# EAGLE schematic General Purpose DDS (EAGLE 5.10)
MFG: Kemet; PN: A700V106M016ATE045

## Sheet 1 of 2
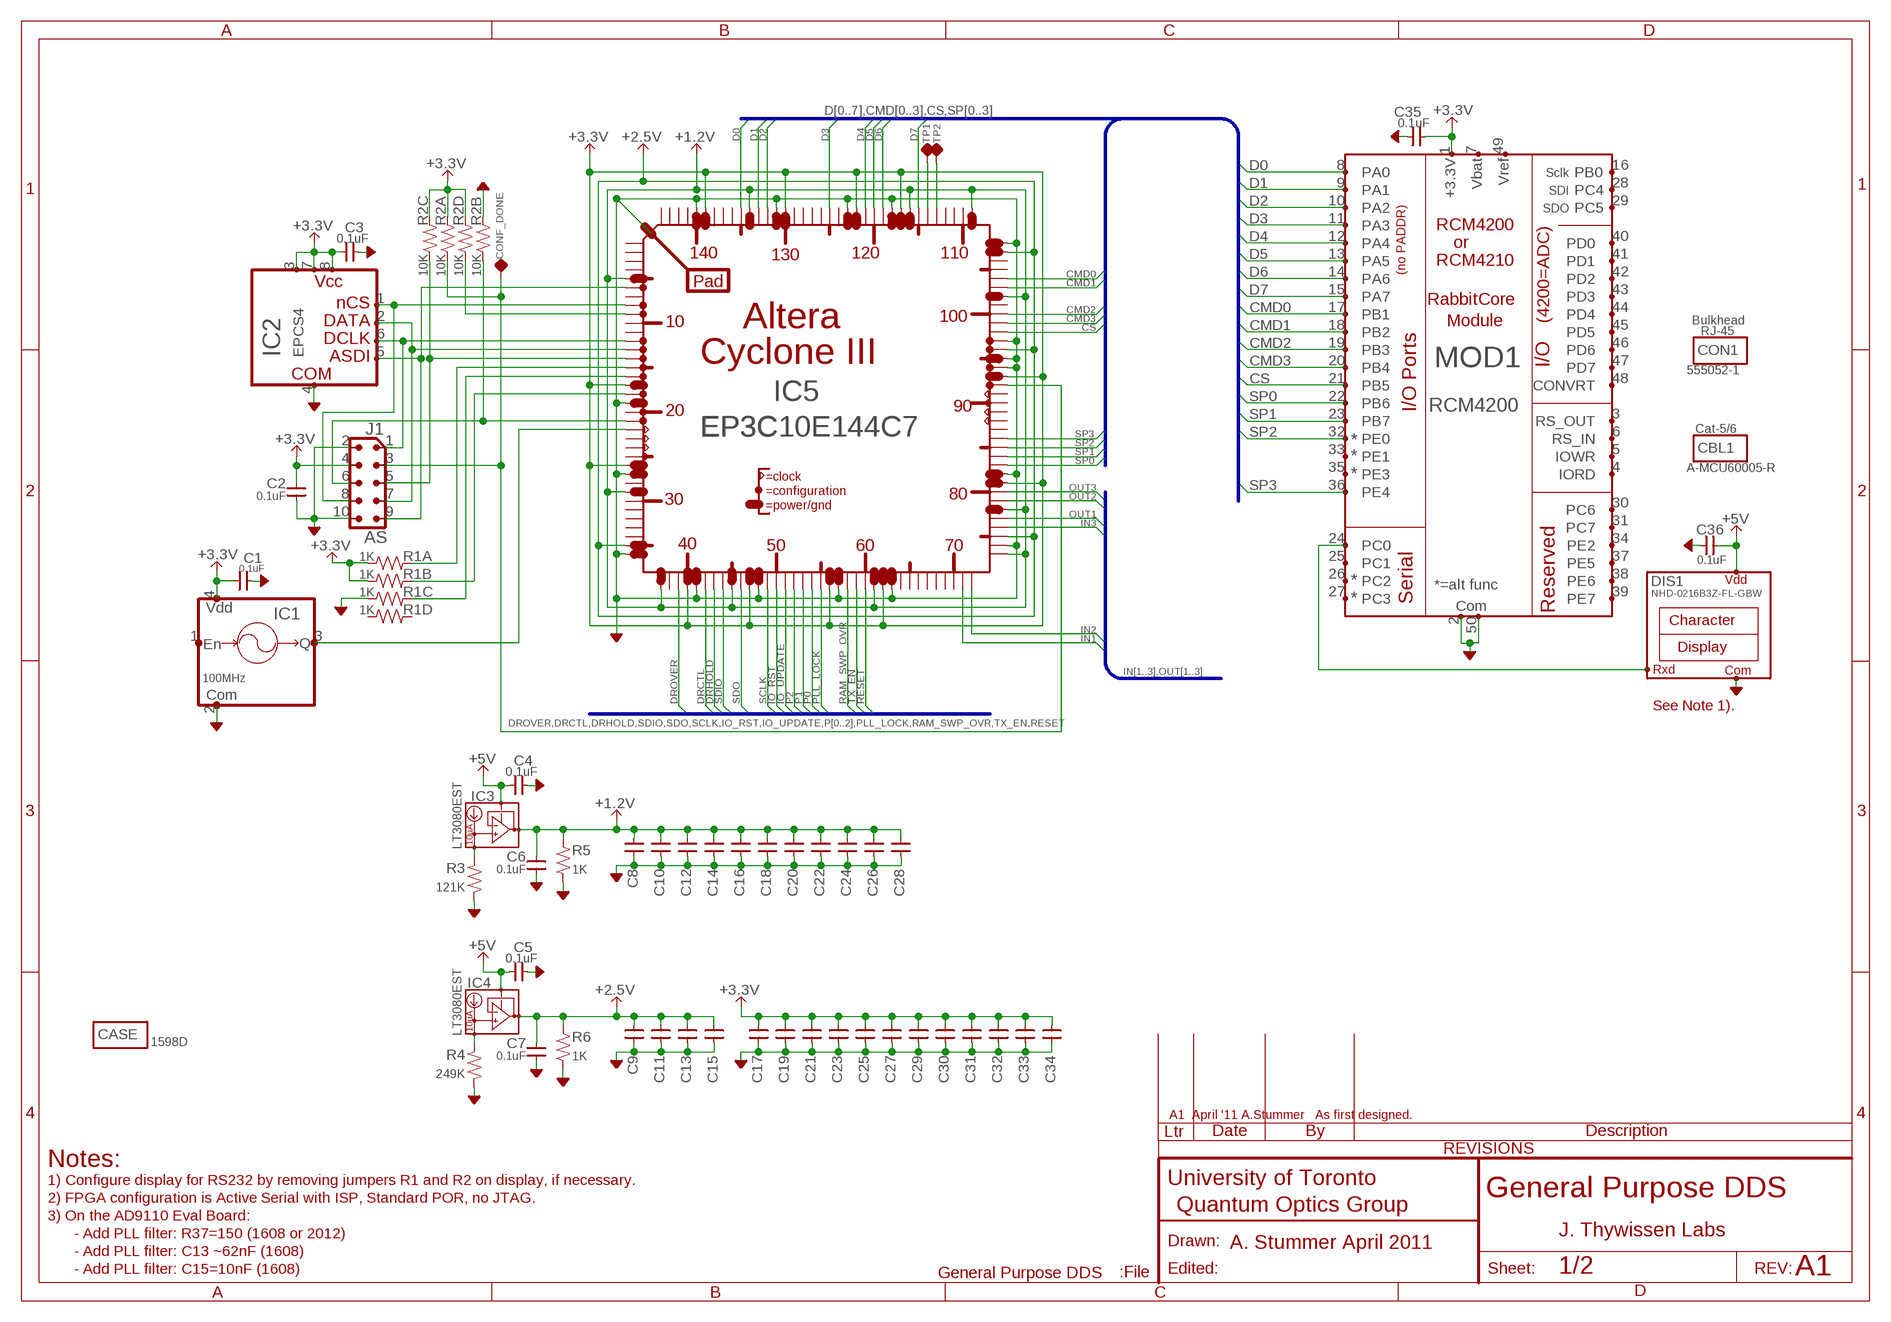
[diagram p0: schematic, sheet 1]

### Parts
C1  0.1uF  CAP-H-0805  [2012(0805)]
C2  0.1uF  CAP-V-0805  [2012(0805)]
C3  0.1uF  CAP-H-0805  [2012(0805)]
C4  0.1uF  CAP-H-0805  [2012(0805)]
C5  0.1uF  CAP-H-0805  [2012(0805)]
C6  0.1uF  CAP-V-0805  [2012(0805)]
C7  0.1uF  CAP-V-0805  [2012(0805)]
C8  0.1uF  CAP-V-0603  [1608(0603)]
C9  0.1uF  CAP-V-0603  [1608(0603)]
C10  0.1uF  CAP-V-0603  [1608(0603)]
C11  0.1uF  CAP-V-0603  [1608(0603)]
C12  0.1uF  CAP-V-0603  [1608(0603)]
C13  0.1uF  CAP-V-0603  [1608(0603)]
C14  0.1uF  CAP-V-0603  [1608(0603)]
C15  0.1uF  CAP-V-0603  [1608(0603)]
C16  0.1uF  CAP-V-0603  [1608(0603)]
C17  0.1uF  CAP-V-0603  [1608(0603)]
C18  0.1uF  CAP-V-0603  [1608(0603)]
C19  0.1uF  CAP-V-0603  [1608(0603)]
C20  0.1uF  CAP-V-0603  [1608(0603)]
C21  0.1uF  CAP-V-0603  [1608(0603)]
C22  0.1uF  CAP-V-0603  [1608(0603)]
C23  0.1uF  CAP-V-0603  [1608(0603)]
C24  0.1uF  CAP-V-0603  [1608(0603)]
C25  0.1uF  CAP-V-0603  [1608(0603)]
C26  0.1uF  CAP-V-0603  [1608(0603)]
C27  0.1uF  CAP-V-0603  [1608(0603)]
C28  0.1uF  CAP-V-0603  [1608(0603)]
C29  0.1uF  CAP-V-0603  [1608(0603)]
C30  0.1uF  CAP-V-0603  [1608(0603)]
C31  0.1uF  CAP-V-0603  [1608(0603)]
C32  0.1uF  CAP-V-0603  [1608(0603)]
C33  0.1uF  CAP-V-0603  [1608(0603)]
C34  0.1uF  CAP-V-0603  [1608(0603)]
C35  0.1uF  CAP-H-0805  [2012(0805)]
C36  0.1uF  CAP-H-0805  [2012(0805)]
CASE  1598D  MISC  [MISC]
CBL1  A-MCU60005-R  MISC  [MISC]
CON1  555052-1  MISC  [MISC]
CONF_DONE  TP-0.042B  [TP-0.042B]
DIS1  NHD-0216B3Z-FL-GBW  DISPLAY:3WIRE  [DISPLAY:3WIRE]
IC1  100MHz  OSCILLATOR:CX750(CITIZEN)-CITIZEN_CSX  [CSX750(CITIZEN_OSC)]
IC2  EPCS4  MEMORY-EPCS1-4(ALTERACONFIG)  [SOIC-8@1]
IC3  LT3080EST  REGULATOR:LT3080(3PIN,LDO,I-SET)-SOT223  [SOT223(C)]
IC4  LT3080EST  REGULATOR:LT3080(3PIN,LDO,I-SET)-SOT223  [SOT223(C)]
IC5  EP3C10E144C7  FPGA_EP3C_T144(CYCLONE3)  [EQFP144(TQFP_WITH_GROUND_PAD)]
J1  CONN-2X5-BLASTER  [CONN-2X5-BLASTER]
MOD1  RCM4200  RABBIT_RCM4200-THROUGH1  [RABBIT_RCM42XX(THRU)]
R1  1K  R-4PAK-0603  [PANASONIC_EXB-V8V(QUAD-R-PACK)]
R2  10K  R-4PAK-0603  [PANASONIC_EXB-V8V(QUAD-R-PACK)]
R3  121K  R-V-0805  [2012(0805)]
R4  249K  R-V-0805  [2012(0805)]
R5  1K  R-V-0805  [2012(0805)]
R6  1K  R-V-0805  [2012(0805)]
TP1  TP-0.042B  [TP-0.042B]
TP2  TP-0.042B  [TP-0.042B]

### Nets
+1.2V: C6.2 C8.2 C10.2 C12.2 C14.2 C16.2 C18.2 C20.2 C22.2 C24.2 C26.2 C28.2 IC3.2(OUT) IC5.5 IC5.29 IC5.37 IC5.45 IC5.61 IC5.73 IC5.78 IC5.102 IC5.109 IC5.116 IC5.134 R5.2
+2.5V: C7.2 C9.2 C11.2 C13.2 C15.2 IC4.2(OUT) IC5.35 IC5.75 IC5.96 IC5.107 R6.2
+3.3V: C1.1 C2.2 C3.1 C17.2 C19.2 C21.2 C23.2 C25.2 C27.2 C29.2 C30.2 C31.2 C32.2 C33.2 C34.2 C35.1 IC1.4(VDD) IC2.3(VCC1) IC2.7(VCC2) IC2.8(VCC3) IC5.17 IC5.26 IC5.40 IC5.47 IC5.56 IC5.62 IC5.81 IC5.93 IC5.117 IC5.122 IC5.130 IC5.139 J1.4 MOD1.1(+3.3V) R1.1A R1.2A R2.1B R2.3B R2.4B ; also sheet 2
+5V: C4.1 C5.1 C36.1 DIS1.VDD IC3.3(IN) IC4.3(IN) ; also sheet 2
AGND: C1.2 C2.1 C3.2 C4.2 C5.2 C6.1 C7.1 C8.1 C9.1 C10.1 C11.1 C12.1 C13.1 C14.1 C15.1 C16.1 C17.1 C18.1 C19.1 C20.1 C21.1 C22.1 C23.1 C24.1 C25.1 C26.1 C27.1 C28.1 C29.1 C30.1 C31.1 C32.1 C33.1 C34.1 C35.2 C36.2 DIS1.COM IC1.2(COM) IC2.4(COM) IC5.19 IC5.27 IC5.36 IC5.41 IC5.48 IC5.57 IC5.63 IC5.74 IC5.82 IC5.94 IC5.95 IC5.97 IC5.108 IC5.118 IC5.123 IC5.131 IC5.140 IC5.PAD J1.2 J1.10 MOD1.2(COM1) MOD1.50(COM2) R1.3A R2.2B R3.1 R4.1 R5.1 R6.1 ; also sheet 2
CMD0: IC5.104 MOD1.17(PB1)
CMD1: IC5.103 MOD1.18(PB2)
CMD2: IC5.100 MOD1.19(PB3)
CMD3: IC5.99 MOD1.20(PB4)
CONF_DONE: CONF_DONE.TP IC5.92 J1.3 R2.1A
CS: IC5.98 MOD1.21(PB5)
D0: IC5.135 MOD1.8(PA0)
D1: IC5.133 MOD1.9(PA1)
D2: IC5.132 MOD1.10(PA2)
D3: IC5.125 MOD1.11(PA3)
D4: IC5.121 MOD1.12(PA4)
D5: IC5.120 MOD1.13(PA5)
D6: IC5.119 MOD1.14(PA6)
D7: IC5.115 MOD1.15(PA7)
DRCTL: IC5.42 ; also sheet 2
DRHOLD: IC5.43 ; also sheet 2
DROVER: IC5.39 ; also sheet 2
IN1: IC5.71 ; also sheet 2
IN2: IC5.72 ; also sheet 2
IN3: IC5.76 ; also sheet 2
IO_RST: IC5.50 ; also sheet 2
IO_UPDATE: IC5.51 ; also sheet 2
N$1: IC2.2(DATA) IC5.13 J1.7
N$2: IC2.6(DCLK) IC5.12 J1.1
N$3: IC2.1(NCS) IC5.8 J1.8
N$4: IC2.5(ASDI) IC5.6 J1.9
N$6: IC5.14 J1.5 R2.3A
N$7: IC5.21 J1.6 R2.2A
N$9: IC5.16 R1.3B
N$11: IC5.9 R2.4A
N$12: IC5.18 R1.2B
N$13: IC5.15 R1.1B
N$16: IC1.3(Q) IC5.22
N$29: IC3.1(SET) R3.2
N$30: DIS1.RXD MOD1.24(PC0)
N$32: IC4.1(SET) R4.2
N$62: IC5.114 TP1.TP
N$66: IC5.113 TP2.TP
OUT1: IC5.77 ; also sheet 2
OUT2: IC5.79 ; also sheet 2
OUT3: IC5.80 ; also sheet 2
P0: IC5.54 ; also sheet 2
P1: IC5.53 ; also sheet 2
P2: IC5.52 ; also sheet 2
PLL_LOCK: IC5.55 ; also sheet 2
RAM_SWP_OVR: IC5.58 ; also sheet 2
RESET: IC5.60 ; also sheet 2
SCLK: IC5.49 ; also sheet 2
SDIO: IC5.44 ; also sheet 2
SDO: IC5.46 ; also sheet 2
SP0: IC5.83 MOD1.22(PB6)
SP1: IC5.84 MOD1.23(PB7)
SP2: IC5.85 MOD1.32(PE0)
SP3: IC5.86 MOD1.36(PE4)
TX_EN: IC5.59 ; also sheet 2
Unconnected: IC1.1(EN) IC5.1 IC5.2 IC5.3 IC5.4 IC5.7 IC5.10 IC5.11 IC5.20 IC5.23 IC5.24 IC5.25 IC5.28 IC5.30 IC5.31 IC5.32 IC5.33 IC5.34 IC5.38 IC5.64 IC5.65 IC5.66 IC5.67 IC5.68 IC5.69 IC5.70 IC5.87 IC5.88 IC5.89 IC5.90 IC5.91 IC5.101 IC5.105 IC5.106 IC5.110 IC5.111 IC5.112 IC5.124 IC5.126 IC5.127 IC5.128 IC5.129 IC5.136 IC5.137 IC5.138 IC5.141 IC5.142 IC5.143 IC5.144 MOD1.3(RS_OUT) MOD1.4(IORD) MOD1.5(IOWR) MOD1.6(RS_IN) MOD1.7(VBAT) MOD1.16(PB0) MOD1.25(PC1) MOD1.26(PC2) MOD1.27(PC3) MOD1.28(PC4) MOD1.29(PC5) MOD1.30(PC6) MOD1.31(PC7) MOD1.33(PE1) MOD1.34(PE2) MOD1.35(PE3) MOD1.37(PE5) MOD1.38(PE6) MOD1.39(PE7) MOD1.40(PD0) MOD1.41(PD1) MOD1.42(PD2) MOD1.43(PD3) MOD1.44(PD4) MOD1.45(PD5) MOD1.46(PD6) MOD1.47(PD7) MOD1.48(CONVRT) MOD1.49(VREF) R1.4A R1.4B

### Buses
DROVER,DRCTL,DRHOLD,SDIO,SDO,SCLK,IO_RST,IO_UPDATE,P[0..2],PLL_LOCK,RAM_SWP_OVR,TX_EN,RESET
RABBIT:D[0..7],CMD[0..3],CS,SP[0..3]
IN[1..3],OUT[1..3]
D[0..7],CMD[0..3],CS,SP[0..3]

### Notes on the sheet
- Bulkhead
- RJ-45
- Cat-5/6
- AS
- See Note 1).
- A1  April '11 A.Stummer   As first designed.
- Notes:
- 1) Configure display for RS232 by removing jumpers R1 and R2 on display, if necessary.
- General Purpose DDS
- 2) FPGA configuration is Active Serial with ISP, Standard POR, no JTAG.
- 3) On the AD9110 Eval Board:
- - Add PLL filter: R37=150 (1608 or 2012) | J. Thywissen Labs
- A. Stummer April 2011
- - Add PLL filter: C13 ~62nF (1608)
- - Add PLL filter: C15=10nF (1608) | A1

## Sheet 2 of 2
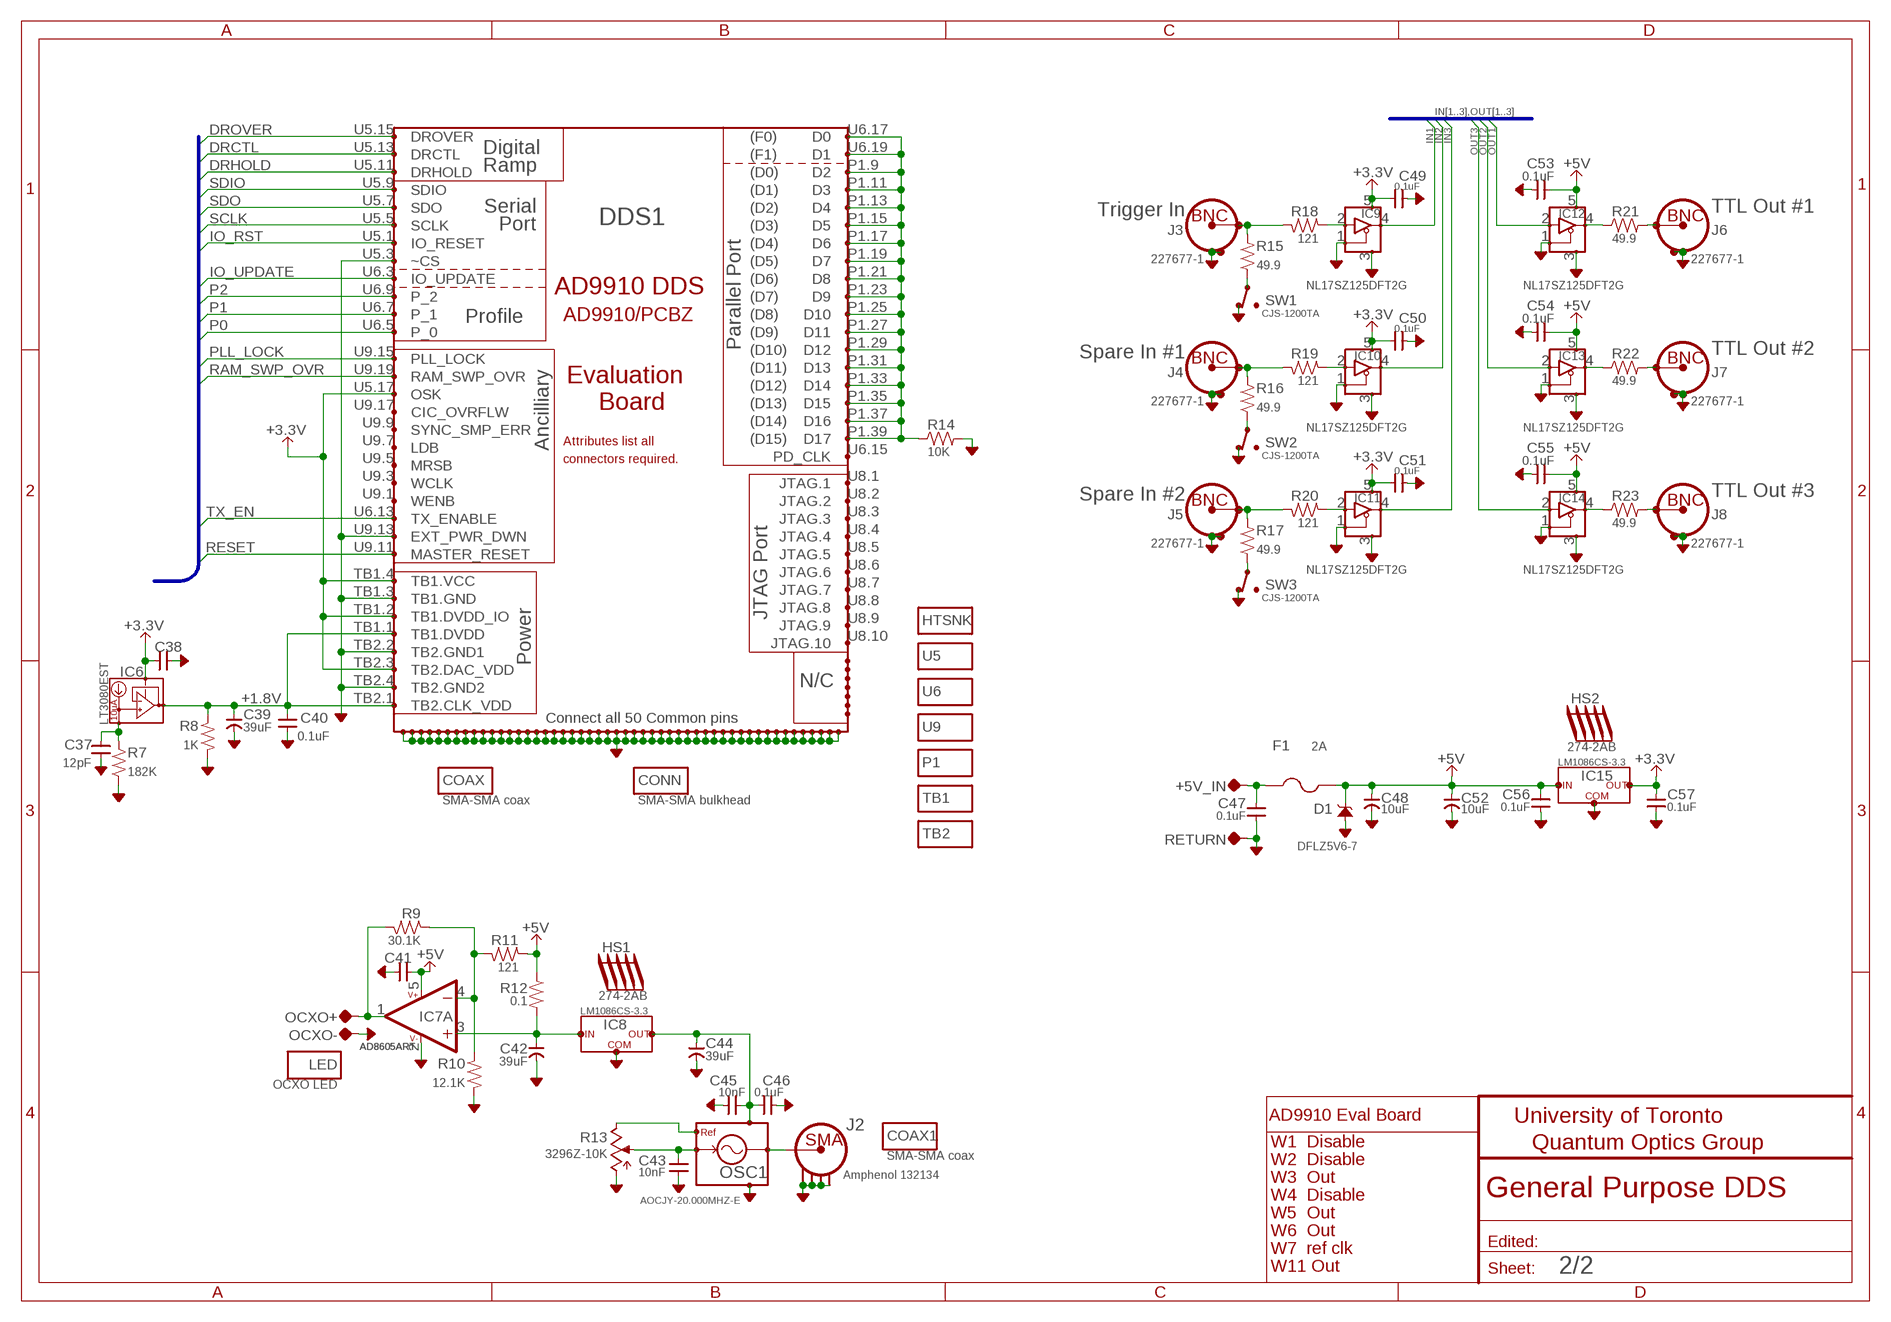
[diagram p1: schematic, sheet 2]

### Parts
+5V_IN  TP-0.042B  [TP-0.042B]
C37  12pF  CAP-H-0805  [2012(0805)]
C38  0.1uF  CAP-H-0805  [2012(0805)]
C39  39uF  CAP-POL--NIPPONCHEM_E61  [CAP:NIPPONCHEM_E61]
C40  0.1uF  CAP-H-0805  [2012(0805)]
C41  0.1uF  CAP-H-0805  [2012(0805)]
C42  39uF  CAP-POL--NIPPONCHEM_E61  [CAP:NIPPONCHEM_E61]
C43  10nF  CAP-H-0805  [2012(0805)]
C44  39uF  CAP-POL--NIPPONCHEM_E61  [CAP:NIPPONCHEM_E61]
C45  10nF  CAP-H-0805  [2012(0805)]
C46  0.1uF  CAP-H-0805  [2012(0805)]
C47  0.1uF  CAP-V-0805  [2012(0805)]
C48  10uF  CAP-POL-EIA-7343-13  [EIA-7343]
C49  0.1uF  CAP-H-0805  [2012(0805)]
C50  0.1uF  CAP-H-0805  [2012(0805)]
C51  0.1uF  CAP-H-0805  [2012(0805)]
C52  10uF  CAP-POL-EIA-7343-13  [EIA-7343]
C53  0.1uF  CAP-H-0805  [2012(0805)]
C54  0.1uF  CAP-H-0805  [2012(0805)]
C55  0.1uF  CAP-H-0805  [2012(0805)]
C56  0.1uF  CAP-V-0805  [2012(0805)]
C57  0.1uF  CAP-V-0805  [2012(0805)]
COAX  SMA-SMA coax  MISC  [MISC]
COAX1  SMA-SMA coax  MISC  [MISC]
CONN  SMA-SMA bulkhead  MISC  [MISC]
D1  DFLZ5V6-7  ZENER-DFLZ  [ZENER:DFLZ_V_(1W)]
DDS1  DDS:AD9910,EVALBOARD  [DDS:AD9910,EVALBOARD]
F1  2A  FUSE-5X20-4  [FUSE]
HS1  274-2AB  HEATSINK-1-274AB  [HEATSINK:274-2AB(WAKEFIELD,25C/W)]
HS2  274-2AB  HEATSINK-1-274AB  [HEATSINK:274-2AB(WAKEFIELD,25C/W)]
HTSNK  MISC  [MISC]
IC6  LT3080EST  REGULATOR:LT3080(3PIN,LDO,I-SET)-SOT223  [SOT223(C)]
IC7  AD8605ART  OPAMP-SOT23-5  [SOT23-5]
IC8  LM1086CS-3.3  REGULATOR:LM1086(LDO)-TO263  [TO263]
IC9  NL17SZ125DFT2G  LOGIC,BUFFER:NL17SZ125/16(SINGLE,BI-TRI-STATE)-SOT353  [SOT353]
IC10  NL17SZ125DFT2G  LOGIC,BUFFER:NL17SZ125/16(SINGLE,BI-TRI-STATE)-SOT353  [SOT353]
IC11  NL17SZ125DFT2G  LOGIC,BUFFER:NL17SZ125/16(SINGLE,BI-TRI-STATE)-SOT353  [SOT353]
IC12  NL17SZ125DFT2G  LOGIC,BUFFER:NL17SZ125/16(SINGLE,BI-TRI-STATE)-SOT353  [SOT353]
IC13  NL17SZ125DFT2G  LOGIC,BUFFER:NL17SZ125/16(SINGLE,BI-TRI-STATE)-SOT353  [SOT353]
IC14  NL17SZ125DFT2G  LOGIC,BUFFER:NL17SZ125/16(SINGLE,BI-TRI-STATE)-SOT353  [SOT353]
IC15  LM1086CS-3.3  REGULATOR:LM1086(LDO)-TO263  [TO263]
J2  Amphenol 132134  CONN:SMA  [CONN:SMA1]
J3  227677-1  CONN-BNCTYPE3HORIZ  [CONN-BNC-AMP-TYPE3HORIZ]
J4  227677-1  CONN-BNCTYPE3HORIZ  [CONN-BNC-AMP-TYPE3HORIZ]
J5  227677-1  CONN-BNCTYPE3HORIZ  [CONN-BNC-AMP-TYPE3HORIZ]
J6  227677-1  CONN-BNCTYPE3HORIZ  [CONN-BNC-AMP-TYPE3HORIZ]
J7  227677-1  CONN-BNCTYPE3HORIZ  [CONN-BNC-AMP-TYPE3HORIZ]
J8  227677-1  CONN-BNCTYPE3HORIZ  [CONN-BNC-AMP-TYPE3HORIZ]
LED  OCXO LED  MISC  [MISC]
OCXO+  TP-0.042B  [TP-0.042B]
OCXO-  TP-0.042B  [TP-0.042B]
OSC1  AOCJY-20.000MHZ-E  OSCILLATOR:AOCJY(ABRACON-OCXO)  [OSCILLATOR:AOCJY(ABRACON-OCXO)]
P1  MISC  [MISC]
R7  182K  R-V-0805  [2012(0805)]
R8  1K  R-V-0805  [2012(0805)]
R9  30.1K  R-H-0805  [2012(0805)]
R10  12.1K  R-V-0805  [2012(0805)]
R11  121  R-H-0805  [2012(0805)]
R12  0.1  R-H-0805  [2012(0805)]
R13  3296Z-10K  POT-BOURNS_3296Y  [BOURNS:3296Y]
R14  10K  R-H-0805  [2012(0805)]
R15  49.9  R-V-0805  [2012(0805)]
R16  49.9  R-V-0805  [2012(0805)]
R17  49.9  R-V-0805  [2012(0805)]
R18  121  R-H-0805  [2012(0805)]
R19  121  R-H-0805  [2012(0805)]
R20  121  R-H-0805  [2012(0805)]
R21  49.9  R-H-0805  [2012(0805)]
R22  49.9  R-H-0805  [2012(0805)]
R23  49.9  R-H-0805  [2012(0805)]
RETURN  TP-0.042B  [TP-0.042B]
SW1  CJS-1200TA  SWITCH:SPDT_CJS-1200A1  [SWITCH:SPDT-DIP(COPAL)]
SW2  CJS-1200TA  SWITCH:SPDT_CJS-1200A1  [SWITCH:SPDT-DIP(COPAL)]
SW3  CJS-1200TA  SWITCH:SPDT_CJS-1200A1  [SWITCH:SPDT-DIP(COPAL)]
TB1  MISC  [MISC]
TB2  MISC  [MISC]
U5  MISC  [MISC]
U6  MISC  [MISC]
U9  MISC  [MISC]

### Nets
+1.8V [Power]: C39.POS C40.1 DDS1.TB1.1(TB1.DVDD) DDS1.TB2.1(TB2.CLK_VDD) IC6.2(OUT) R8.2
+3.3V: C38.1 C49.1 C50.1 C51.1 C57.2 DDS1.TB1.2(TB1.DVDD_IO) DDS1.TB1.4(TB1.VCC) DDS1.TB2.3(TB2.DAC_VDD) DDS1.U5.17(OSK) IC6.3(IN) IC9.5(VDD) IC10.5(VDD) IC11.5(VDD) IC15.2(OUT) ; also sheet 1
+5V: C41.1 C48.+(POS) C52.+(POS) C53.1 C54.1 C55.1 C56.2 D1.C F1.2A IC7.5(B:V++) IC12.5(VDD) IC13.5(VDD) IC14.5(VDD) IC15.3(VI) R11.1 R12.1 ; also sheet 1
AGND: C37.2 C38.2 C39.NEG C40.2 C41.2 C42.NEG C43.2 C44.NEG C45.2 C46.2 C47.1 C48.-(NEG) C49.2 C50.2 C51.2 C52.-(NEG) C53.2 C54.2 C55.2 C56.1 C57.1 D1.A DDS1.P1.2(G1) DDS1.P1.4(G2) DDS1.P1.6(G3) DDS1.P1.8(G4) DDS1.P1.10(G5) DDS1.P1.12(G6) DDS1.P1.14(G7) DDS1.P1.16(G8) DDS1.P1.18(G9) DDS1.P1.20(G10) DDS1.P1.22(G11) DDS1.P1.24(G12) DDS1.P1.26(G13) DDS1.P1.28(G14) DDS1.P1.30(G15) DDS1.P1.32(G16) DDS1.P1.34(G17) DDS1.P1.36(G18) DDS1.P1.38(G19) DDS1.P1.40(G20) DDS1.TB1.3(TB1.GND) DDS1.TB2.2(TB2.GND1) DDS1.TB2.4(TB2.GND2) DDS1.U5.2(G31) DDS1.U5.3(~CS) DDS1.U5.4(G32) DDS1.U5.6(G33) DDS1.U5.8(G34) DDS1.U5.10(G35) DDS1.U5.12(G36) DDS1.U5.14(G37) DDS1.U5.16(G38) DDS1.U5.18(G39) DDS1.U5.20(G40) DDS1.U6.2(G21) DDS1.U6.4(G22) DDS1.U6.6(G23) DDS1.U6.8(G24) DDS1.U6.10(G25) DDS1.U6.12(G26) DDS1.U6.14(G27) DDS1.U6.16(G28) DDS1.U6.18(G29) DDS1.U6.20(G30) DDS1.U9.2(G41) DDS1.U9.4(G42) DDS1.U9.6(G43) DDS1.U9.8(G44) DDS1.U9.10(G45) DDS1.U9.12(G46) DDS1.U9.13(EXT_PWR_DWN) DDS1.U9.14(G47) DDS1.U9.16(G48) DDS1.U9.18(G49) DDS1.U9.20(G50) IC7.2(B:V-) IC8.1(COM) IC9.1(OE) IC9.3(COM) IC10.1(OE) IC10.3(COM) IC11.1(OE) IC11.3(COM) IC12.1(OE) IC12.3(COM) IC13.1(OE) IC13.3(COM) IC14.1(OE) IC14.3(COM) IC15.1(COM) J2.COM1 J2.COM2 J2.COM3 J2.COM4 J3.SHIELD1 J3.SHIELD2 J4.SHIELD1 J4.SHIELD2 J5.SHIELD1 J5.SHIELD2 J6.SHIELD1 J6.SHIELD2 J7.SHIELD1 J7.SHIELD2 J8.SHIELD1 J8.SHIELD2 OCXO-.TP OSC1.COM R7.1 R8.1 R10.1 R13.CCW R14.2 RETURN.TP SW1.2(NC\DOWN\LEFT) SW2.2(NC\DOWN\LEFT) SW3.2(NC\DOWN\LEFT) ; also sheet 1
DRCTL: DDS1.U5.13(DRCTL) ; also sheet 1
DRHOLD: DDS1.U5.11(DRHOLD) ; also sheet 1
DROVER: DDS1.U5.15(DROVER) ; also sheet 1
IN1: IC9.4(OUT) ; also sheet 1
IN2: IC10.4(OUT) ; also sheet 1
IN3: IC11.4(OUT) ; also sheet 1
IO_RST: DDS1.U5.1(IO_RESET) ; also sheet 1
IO_UPDATE: DDS1.U6.3(IO_UPDATE) ; also sheet 1
N$5: +5V_IN.TP C47.2 F1.1A
N$8: R15.1 SW1.COM
N$10: R16.1 SW2.COM
N$14: C42.POS IC7.3(A:+IN) IC8.3(VI) R12.2
N$15: J2.CONDUCTOR OSC1.OUT
N$17: C43.1 OSC1.CTRL R13.W
N$18: OSC1.VREF R13.CW
N$19: C44.POS C45.1 C46.1 IC8.2(OUT) OSC1.VDD(VCC)
N$20: IC7.1(A:OUT) OCXO+.TP R9.2
N$21: J3.CONDUCTOR R15.2 R18.2
N$22: IC9.2(IN) R18.1
N$23: J4.CONDUCTOR R16.2 R19.2
N$24: IC10.2(IN) R19.1
N$25: J6.CONDUCTOR R21.2
N$26: IC12.4(OUT) R21.1
N$27: J7.CONDUCTOR R22.2
N$28: IC13.4(OUT) R22.1
N$31: IC7.4(A:-IN) R9.1 R10.2 R11.2
N$33: DDS1.P1.9(D2) DDS1.P1.11(D3) DDS1.P1.13(D4) DDS1.P1.15(D5) DDS1.P1.17(D6) DDS1.P1.19(D7) DDS1.P1.21(D8) DDS1.P1.23(D9) DDS1.P1.25(D10) DDS1.P1.27(D11) DDS1.P1.29(D12) DDS1.P1.31(D13) DDS1.P1.33(D14) DDS1.P1.35(D15) DDS1.P1.37(D16) DDS1.P1.39(D17) DDS1.U6.17(D0) DDS1.U6.19(D1) R14.1
N$34: R17.1 SW3.COM
N$35: J5.CONDUCTOR R17.2 R20.2
N$36: IC11.2(IN) R20.1
N$37: J8.CONDUCTOR R23.2
N$38: IC14.4(OUT) R23.1
N$42: C37.1 IC6.1(SET) R7.2
OUT1: IC12.2(IN) ; also sheet 1
OUT2: IC13.2(IN) ; also sheet 1
OUT3: IC14.2(IN) ; also sheet 1
P0: DDS1.U6.5(P_0) ; also sheet 1
P1: DDS1.U6.7(P_1) ; also sheet 1
P2: DDS1.U6.9(P_2) ; also sheet 1
PLL_LOCK: DDS1.U9.15(PLL_LOCK) ; also sheet 1
RAM_SWP_OVR: DDS1.U9.19(RAM_SWP_OVR) ; also sheet 1
RESET: DDS1.U9.11(MASTER_RESET) ; also sheet 1
SCLK: DDS1.U5.5(SCLK) ; also sheet 1
SDIO: DDS1.U5.9(SDIO) ; also sheet 1
SDO: DDS1.U5.7(SDO) ; also sheet 1
TX_EN: DDS1.U6.13(TX_ENABLE) ; also sheet 1
Unconnected: DDS1.P1.1(NC1) DDS1.P1.3(NC2) DDS1.P1.5(NC3) DDS1.P1.7(NC4) DDS1.U5.19(NC7) DDS1.U6.1(NC5) DDS1.U6.11(NC6) DDS1.U6.15(PD_CLK) DDS1.U8.1(JTAG.1) DDS1.U8.2(JTAG.2) DDS1.U8.3(JTAG.3) DDS1.U8.4(JTAG.4) DDS1.U8.5(JTAG.5) DDS1.U8.6(JTAG.6) DDS1.U8.7(JTAG.7) DDS1.U8.8(JTAG.8) DDS1.U8.9(JTAG.9) DDS1.U8.10(JTAG.10) DDS1.U9.1(WENB) DDS1.U9.3(WCLK) DDS1.U9.5(MRSB) DDS1.U9.7(LDB) DDS1.U9.9(SYNC_SMP_ERR) DDS1.U9.17(CIC_OVRFLW) SW1.1(NO\UP\RIGHT) SW2.1(NO\UP\RIGHT) SW3.1(NO\UP\RIGHT)

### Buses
DROVER,DRCTL,DRHOLD,SDIO,SDO,SCLK,IO_RST,IO_UPDATE,P[0..2],PLL_LOCK,RAM_SWP_OVR,TX_EN,RESET
IN[1..3],OUT[1..3]

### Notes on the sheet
- Trigger In | TTL Out #1
- Spare In #1 | TTL Out #2
- Spare In #2 | TTL Out #3
- AD9910 Eval Board
- W1  Disable
- W2  Disable
- W3  Out
- W4  Disable | General Purpose DDS
- W5  Out
- W6  Out
- W7  ref clk
- W11 Out

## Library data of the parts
+5V_IN CONF_DONE OCXO+ OCXO- RETURN TP1 TP2 = QuantumOptics:TP: Testpoint, either SMT pad, small hole or loop style TP such as Keystone 5002K (0.042").
C1 C3-C5 C35-C38 C40 C41 C43 C45 C46 C49-C51 C53-C55 = QuantumOptics:CAP-H-: Cap, SMT and Through-hole, 0402 and up.
C2 C6-C34 C47 C56 C57 = QuantumOptics:CAP-V-: Cap, SMT and Through-hole, 0402 and up.
C39 C42 C44 C48 C52 = QuantumOptics:CAP-POL-: Capacitor, Polarized, SMT 0805 and up, probably tantalum.
CASE CBL1 COAX COAX1 CON1 CONN HTSNK LED P1 TB1 TB2 U5 U6 U9 = QuantumOptics:MISC: Miscellaneous Part, just a placeholder for miscellaeous parts
D1 = QuantumOptics:ZENER: Zener
DDS1 = QuantumOptics:DDS:AD9910,EVALBOARD: AD9910 DDS Eval Board, Rev:G, Analog Devices 1GSPS 14-bit 3.3V, can ramp to fixed stop frequency. http://www.analog.com/en/rfif-components/direct-digital-synthesis-dds/ad9910/products/product.html; P1: P1: Samtec SSW-120-01-G-D; TB1-2: TB1,2: Pheonix 1792032; U569: U5,6,9: Samtec SSW-110-01-G-D; U8: U8: Samtec SSW-108-01-G-D
DIS1 = QuantumOptics:DISPLAY:3WIRE: LCD display module, serial (RS232, I2C or SPI), actually just the connector. e.g. Newhaven Display Intl NHD-0216B3Z-FL-GBW http://www.newhavendisplay.com/pdf/nhd-0216b3z-fl-gbw.pdf
F1 = QuantumOptics:FUSE: Fuse
HS1 HS2 = QuantumOptics:HEATSINK-1: Heatsink, no connections to heatsink.
IC1 = QuantumOptics:OSCILLATOR:CX750(CITIZEN): CSX750 Oscillators, Citizen, +3.3V or +5V, 1MHZ to 133MHz. http://www.citizencrystal.com/images/pdf/os-csx750f.pdf
IC2 = QuantumOptics:MEMORY-EPCS1-4(ALTERACONFIG): EPCS1 or EPCS4, Altera, FPGA serial configuration device.
IC3 IC4 IC6 = QuantumOptics:REGULATOR:LT3080(3PIN,LDO,I-SET): LT3080, LDO, output set by single resistor, nice part, LinTech, 1A, SOT223, MSOP8, TO220. http://cds.linear.com/docs/Datasheet/3080f.pdf
IC5 = QuantumOptics:FPGA_EP3C_T144(CYCLONE3): EP3CxxT144xx, Cyclone III FPGA, Altera. Only QFP available.
IC7 = QuantumOptics:OPAMP: Op Amp, generic, pick the right package. e.g. AD8605: SOT-23-5, RRIO, 10MHz, Ib = 1pA, Vio < 65uV, 2.7-5.5V.
IC8 IC15 = QuantumOptics:REGULATOR:LM1086(LDO): LM1086-xxx, National Semiconductor, LDO, adjustable or fixed. http://cache.national.com/ds/LM/LM1086.pdf
IC9-IC14 = QuantumOptics:LOGIC,BUFFER:NL17SZ125/16(SINGLE,BI-TRI-STATE): NL17SZ125/16 buffer, OnSemi, tri(125) or bi(16) state, also NC7SZ125/16. http://www.onsemi.com/pub_link/Collateral/NL17SZ125-D.PDF
J1 = QuantumOptics:CONN-2X5-BLASTER: Connector, 2 rows of 5 for ByteBlaster, USBBlaster or MasterBlaster, on 0.1" grid, pins numbering zig-zags top-left to bottom-right.
J2 = QuantumOptics:CONN:SMA: SMA PCB Connector.
J3-J8 = QuantumOptics:CONN-BNC: BNC PCB, horizontal or vertical, e.g. vertical: Amp 227677-1, nut 1-329631-2, shoulder washer 330620. The two shield connections allow the assembly on either side of the board. Horiz isolated: 5227222-6, http://catalog.tycoelectronics.com/TE/bin/TE.Connect?C=1&M=BYPN&TCPN=5227222-6&RQPN=5227222-6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
MOD1 = QuantumOptics:RABBIT_RCM4200: RCM4200 Rabbit core module Must order connector Samtec SFM(L)-125-01-S-D (if no -125- use -130 30-position and cut short).; THROUGH_CONN: Samtec SFML-125-01-S-D
OSC1 = QuantumOptics:OSCILLATOR:AOCJY(ABRACON-OCXO): OCXO, Abracon AOCJY series, ±5ppb/°, +3.3V.
R1 R2 = QuantumOptics:R-4PAK: Quad Resistor Pack
R3-R8 R10 R15-R17 = QuantumOptics:R-V-*: Resistor, SMT & Through-Hole, vertical symbol
R9 R11 R12 R14 R18-R23 = QuantumOptics:R-H-*: Resistor, SMT & Through-Hole, horizontal symbol
R13 = QuantumOptics:POT: Pot, regular or trimpot
SW1-SW3 = QuantumOptics:SWITCH:SPDT: Switch, SPDT

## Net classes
0 default: width 0.178 mm, drill 0.508 mm, clearance 0.178 mm
1 Power: width 0.356 mm, drill 0.711 mm, clearance 0.178 mm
